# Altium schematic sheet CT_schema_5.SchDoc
size 287 x 160 mm
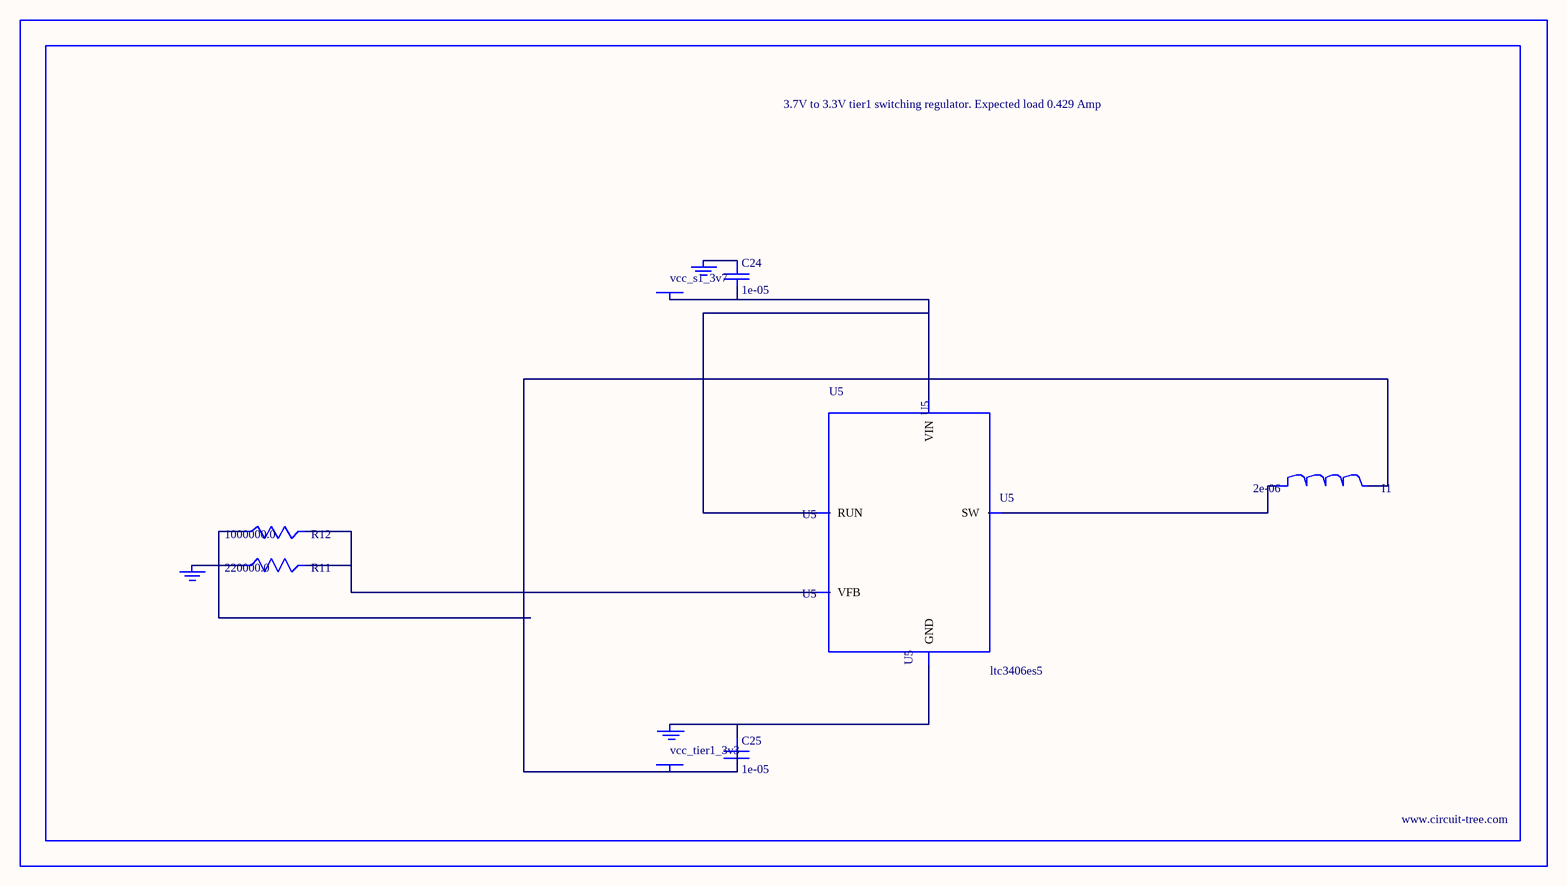
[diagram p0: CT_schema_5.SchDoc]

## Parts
BORDER4  (no value)
C24  1e-05  [C0805]
C25  1e-05  [C0805]
GND_INSTANCE_4_0  (no value)
GND_INSTANCE_4_1  (no value)
GND_INSTANCE_4_2  (no value)
I1  2e-06  [WE-HCI_7030/7040/7050]
POWER_INSTANCE_4_0  vcc_tier1_3v3
POWER_INSTANCE_4_1  vcc_s1_3v7
R11  220000.0  [R0603]
R12  1000000.0  [R0603]
U5  ltc3406es5  [TSOT-23-5]

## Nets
NetC24_1: C24.1 GND_INSTANCE_4_1.0(GND)
NetC24_2: C24.2 POWER_INSTANCE_4_1.0(PWR) U5.1(RUN) U5.4(VIN)
NetC25_1: C25.1 GND_INSTANCE_4_0.0(GND) U5.2(GND)
NetC25_2: C25.2 I1.2 POWER_INSTANCE_4_0.0(PWR) R12.1
NetGND_INSTANCE_4_2_0: GND_INSTANCE_4_2.0(GND) R11.1
NetI1_1: I1.1 U5.3(SW)
NetR11_2: R11.2 R12.2 U5.5(VFB)

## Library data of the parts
BORDER4 = BORDER_PAGE4
C24 C25 = C0805C106K8RACTU
GND_INSTANCE_4_0-GND_INSTANCE_4_2 = GND
I1 = 744314200
POWER_INSTANCE_4_0 POWER_INSTANCE_4_1 = PWR
R11 = RC0603JR-07220KL
R12 = RC0603JR-071ML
